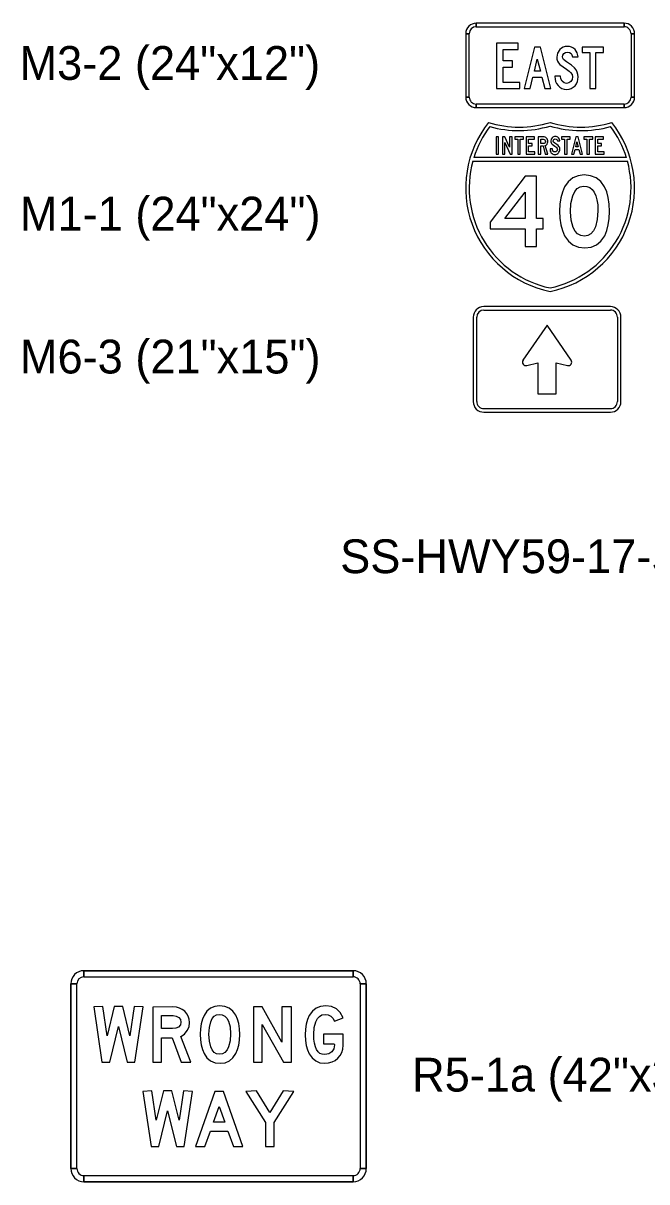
# Model space of a CAD drawing. Extents: x 620856.8 to 620948.6, y 415598.8 to 415658.2.
# Drawn here: x 620913.04 to 620920.43, y 415627.07 to 415640.79 of the extents above; entities that cross this region are included whole.
import ezdxf

# ---------------------------------------------------------------- set-up
doc = ezdxf.new("R2010")
doc.units = 0
doc.layers.add('SIGNS', color=7, linetype='Continuous')

msp = doc.modelspace()

# ---------------------------------------------------------------- linework, layer by layer
at = {"layer": 'SIGNS'}
for p, q in [((620918.405, 415640.745), (620918.405, 415640.787)), ((620920.155, 415640.787), (620920.155, 415640.745)), ((620918.28, 415640.662), (620918.321, 415640.662)), ((620920.238, 415640.662), (620920.28, 415640.662)), ((620918.321, 415639.912), (620918.28, 415639.912)), ((620920.28, 415639.912), (620920.238, 415639.912)), ((620918.405, 415639.787), (620918.405, 415639.829)), ((620920.155, 415639.829), (620920.155, 415639.787)), ((620918.668, 415639.441), (620918.639, 415639.441)), ((620918.639, 415639.441), (620918.639, 415639.236)), ((620918.668, 415639.236), (620918.668, 415639.441)), ((620918.742, 415639.441), (620918.714, 415639.441)), ((620918.714, 415639.441), (620918.714, 415639.236)), ((620918.798, 415639.319), (620918.742, 415639.441)), ((620918.742, 415639.236), (620918.742, 415639.374)), ((620918.742, 415639.374), (620918.806, 415639.236)), ((620918.829, 415639.441), (620918.798, 415639.441)), ((620918.798, 415639.441), (620918.798, 415639.319)), ((620918.829, 415639.236), (620918.829, 415639.441)), ((620918.965, 415639.441), (620918.86, 415639.441)), ((620918.86, 415639.441), (620918.86, 415639.415)), ((620918.86, 415639.415), (620918.897, 415639.415)), ((620918.897, 415639.415), (620918.897, 415639.236)), ((620918.927, 415639.236), (620918.927, 415639.415)), ((620918.927, 415639.415), (620918.965, 415639.415)), ((620918.965, 415639.415), (620918.965, 415639.441)), ((620919.093, 415639.441), (620918.995, 415639.441)), ((620918.995, 415639.441), (620918.995, 415639.236)), ((620919.025, 415639.361), (620919.025, 415639.413)), ((620919.025, 415639.413), (620919.093, 415639.413)), ((620919.068, 415639.361), (620919.025, 415639.361)), ((620919.025, 415639.264), (620919.025, 415639.333)), ((620919.025, 415639.333), (620919.068, 415639.333)), ((620919.068, 415639.333), (620919.068, 415639.361)), ((620919.093, 415639.413), (620919.093, 415639.441)), ((620919.292, 415639.412), (620919.288, 415639.392)), ((620919.288, 415639.392), (620919.289, 415639.382)), ((620919.289, 415639.382), (620919.292, 415639.372)), ((620919.303, 415639.429), (620919.292, 415639.412)), ((620919.292, 415639.372), (620919.297, 415639.364)), ((620919.297, 415639.364), (620919.303, 415639.356)), ((620919.311, 415639.436), (620919.303, 415639.429)), ((620919.303, 415639.356), (620919.337, 415639.332)), ((620919.32, 415639.441), (620919.311, 415639.436)), ((620919.316, 415639.393), (620919.318, 415639.402)), ((620919.317, 415639.386), (620919.316, 415639.393)), ((620919.321, 415639.38), (620919.317, 415639.386)), ((620919.318, 415639.402), (620919.324, 415639.41)), ((620919.33, 415639.444), (620919.32, 415639.441)), ((620919.336, 415639.368), (620919.321, 415639.38)), ((620919.324, 415639.41), (620919.332, 415639.415)), ((620919.34, 415639.445), (620919.33, 415639.444)), ((620919.332, 415639.415), (620919.341, 415639.417)), ((620919.36, 415639.352), (620919.336, 415639.368)), ((620919.337, 415639.332), (620919.349, 415639.323)), ((620919.351, 415639.444), (620919.34, 415639.445)), ((620919.341, 415639.417), (620919.351, 415639.415)), ((620919.349, 415639.323), (620919.357, 415639.316)), ((620919.362, 415639.441), (620919.351, 415639.444)), ((620919.351, 415639.415), (620919.358, 415639.41)), ((620919.358, 415639.41), (620919.362, 415639.403)), ((620919.376, 415639.339), (620919.36, 415639.352)), ((620919.371, 415639.436), (620919.362, 415639.441)), ((620919.362, 415639.403), (620919.366, 415639.393)), ((620919.366, 415639.393), (620919.394, 415639.393)), ((620919.378, 415639.43), (620919.371, 415639.436)), ((620919.384, 415639.329), (620919.376, 415639.339)), ((620919.389, 415639.414), (620919.378, 415639.43)), ((620919.389, 415639.318), (620919.384, 415639.329)), ((620919.394, 415639.393), (620919.389, 415639.414)), ((620919.519, 415639.441), (620919.414, 415639.441)), ((620919.414, 415639.441), (620919.414, 415639.415)), ((620919.414, 415639.415), (620919.451, 415639.415)), ((620919.451, 415639.415), (620919.451, 415639.236)), ((620919.481, 415639.236), (620919.481, 415639.415)), ((620919.481, 415639.415), (620919.519, 415639.415)), ((620919.519, 415639.415), (620919.519, 415639.441)), ((620919.784, 415639.441), (620919.679, 415639.441)), ((620919.679, 415639.441), (620919.679, 415639.415)), ((620919.679, 415639.415), (620919.716, 415639.415)), ((620919.716, 415639.415), (620919.716, 415639.236)), ((620919.746, 415639.236), (620919.746, 415639.415)), ((620919.746, 415639.415), (620919.784, 415639.415)), ((620919.784, 415639.415), (620919.784, 415639.441)), ((620919.911, 415639.441), (620919.814, 415639.441)), ((620919.814, 415639.441), (620919.814, 415639.236)), ((620919.844, 415639.361), (620919.844, 415639.413)), ((620919.844, 415639.413), (620919.911, 415639.413)), ((620919.887, 415639.361), (620919.844, 415639.361)), ((620919.844, 415639.264), (620919.844, 415639.333)), ((620919.844, 415639.333), (620919.887, 415639.333)), ((620919.887, 415639.333), (620919.887, 415639.361)), ((620919.911, 415639.413), (620919.911, 415639.441)), ((620920.183, 415639.195), (620918.376, 415639.195)), ((620918.639, 415639.236), (620918.668, 415639.236)), ((620918.714, 415639.236), (620918.742, 415639.236)), ((620918.806, 415639.236), (620918.829, 415639.236)), ((620918.897, 415639.236), (620918.927, 415639.236)), ((620918.995, 415639.236), (620919.1, 415639.236)), ((620919.1, 415639.264), (620919.025, 415639.264)), ((620919.1, 415639.236), (620919.1, 415639.264)), ((620919.307, 415639.298), (620919.279, 415639.298)), ((620919.279, 415639.298), (620919.279, 415639.296)), ((620919.279, 415639.296), (620919.279, 415639.284)), ((620919.279, 415639.284), (620919.282, 415639.272)), ((620919.282, 415639.272), (620919.287, 415639.261)), ((620919.287, 415639.261), (620919.294, 415639.252)), ((620919.294, 415639.252), (620919.303, 415639.243)), ((620919.303, 415639.243), (620919.313, 415639.237)), ((620919.308, 415639.284), (620919.307, 415639.298)), ((620919.314, 415639.273), (620919.308, 415639.284)), ((620919.313, 415639.237), (620919.324, 415639.234)), ((620919.324, 415639.265), (620919.314, 415639.273)), ((620919.336, 415639.262), (620919.324, 415639.265)), ((620919.324, 415639.234), (620919.336, 415639.232)), ((620919.348, 415639.265), (620919.336, 415639.262)), ((620919.336, 415639.232), (620919.349, 415639.234)), ((620919.358, 415639.272), (620919.348, 415639.265)), ((620919.349, 415639.234), (620919.36, 415639.237)), ((620919.357, 415639.316), (620919.363, 415639.305)), ((620919.364, 415639.282), (620919.358, 415639.272)), ((620919.36, 415639.237), (620919.37, 415639.243)), ((620919.363, 415639.305), (620919.366, 415639.295)), ((620919.366, 415639.295), (620919.364, 415639.282)), ((620919.37, 415639.243), (620919.378, 415639.251)), ((620919.378, 415639.251), (620919.385, 415639.261)), ((620919.385, 415639.261), (620919.39, 415639.271)), ((620919.393, 415639.307), (620919.389, 415639.318)), ((620919.39, 415639.271), (620919.393, 415639.282)), ((620919.394, 415639.295), (620919.393, 415639.307)), ((620919.393, 415639.282), (620919.394, 415639.295)), ((620919.451, 415639.236), (620919.481, 415639.236)), ((620919.716, 415639.236), (620919.746, 415639.236)), ((620919.814, 415639.236), (620919.919, 415639.236)), ((620919.919, 415639.264), (620919.844, 415639.264)), ((620919.919, 415639.236), (620919.919, 415639.264)), ((620919.994, 415637.432), (620918.494, 415637.432)), ((620918.369, 415637.307), (620918.369, 415636.307)), ((620918.41, 415636.307), (620918.41, 415637.307)), ((620918.494, 415637.39), (620919.994, 415637.39)), ((620920.077, 415637.307), (620920.077, 415636.307)), ((620920.119, 415636.307), (620920.119, 415637.307)), ((620919.244, 415637.213), (620918.958, 415636.798)), ((620919.529, 415636.798), (620919.244, 415637.213)), ((620919.003, 415636.735), (620919.134, 415636.765)), ((620919.134, 415636.765), (620919.134, 415636.4)), ((620919.353, 415636.4), (620919.353, 415636.765)), ((620919.353, 415636.765), (620919.484, 415636.735)), ((620919.134, 415636.4), (620919.353, 415636.4)), ((620919.994, 415636.223), (620918.494, 415636.223)), ((620918.494, 415636.182), (620919.994, 415636.182)), ((620916.947, 415629.57), (620913.759, 415629.57)), ((620913.759, 415629.497), (620913.759, 415629.57)), ((620916.947, 415629.57), (620913.759, 415629.57)), ((620913.759, 415629.57), (620916.947, 415629.57)), ((620916.947, 415629.57), (620916.947, 415629.497)), ((620913.603, 415629.414), (620913.603, 415627.227)), ((620913.603, 415629.414), (620913.676, 415629.414)), ((620913.603, 415629.414), (620913.603, 415627.227)), ((620913.603, 415627.227), (620913.603, 415629.414)), ((620917.03, 415629.414), (620917.103, 415629.414)), ((620917.103, 415627.227), (620917.103, 415629.414)), ((620917.103, 415627.227), (620917.103, 415629.414)), ((620917.103, 415629.414), (620917.103, 415627.227)), ((620913.676, 415627.227), (620913.603, 415627.227)), ((620913.759, 415627.07), (620913.759, 415627.143)), ((620916.947, 415627.143), (620916.947, 415627.07)), ((620917.103, 415627.227), (620917.03, 415627.227)), ((620913.759, 415627.07), (620916.947, 415627.07)), ((620913.759, 415627.07), (620916.947, 415627.07)), ((620916.947, 415627.07), (620913.759, 415627.07))]:
    msp.add_line(p, q, dxfattribs=at)
for points in [[(620920.155, 415640.787), (620918.405, 415640.787), (620918.405, 415640.745), (620920.155, 415640.745), (620920.155, 415640.787), (620920.155, 415640.787)], [(620918.28, 415640.662), (620918.28, 415639.912), (620918.321, 415639.912), (620918.321, 415640.662), (620918.28, 415640.662), (620918.28, 415640.662)], [(620920.28, 415639.912), (620920.28, 415640.662), (620920.238, 415640.662), (620920.238, 415639.912), (620920.28, 415639.912), (620920.28, 415639.912)], [(620918.921, 415640.086), (620918.722, 415640.086), (620918.722, 415640.266), (620918.835, 415640.266), (620918.835, 415640.34), (620918.722, 415640.34), (620918.722, 415640.477), (620918.9, 415640.477), (620918.9, 415640.551), (620918.643, 415640.551), (620918.643, 415640.012), (620918.921, 415640.012)], [(620919.336, 415640.159), (620919.336, 415640.155), (620919.338, 415640.125), (620919.345, 415640.097), (620919.357, 415640.072), (620919.374, 415640.049), (620919.395, 415640.028), (620919.419, 415640.014), (620919.446, 415640.005), (620919.475, 415640.002), (620919.504, 415640.005), (620919.531, 415640.014), (620919.554, 415640.028), (620919.575, 415640.047), (620919.592, 415640.07), (620919.603, 415640.095), (620919.61, 415640.122), (620919.613, 415640.152), (620919.61, 415640.181), (620919.602, 415640.208), (620919.588, 415640.233), (620919.569, 415640.257), (620919.532, 415640.289), (620919.475, 415640.328), (620919.437, 415640.357), (620919.429, 415640.371), (620919.426, 415640.387), (620919.431, 415640.409), (620919.444, 415640.428), (620919.463, 415640.44), (620919.486, 415640.444), (620919.51, 415640.44), (620919.528, 415640.429), (620919.537, 415640.412), (620919.545, 415640.387), (620919.613, 415640.387), (620919.602, 415640.437), (620919.576, 415640.477), (620919.557, 415640.492), (620919.535, 415640.503), (620919.511, 415640.51), (620919.484, 415640.512), (620919.459, 415640.51), (620919.436, 415640.503), (620919.414, 415640.491), (620919.395, 415640.474), (620919.367, 415640.433), (620919.358, 415640.385), (620919.36, 415640.361), (620919.367, 415640.338), (620919.379, 415640.317), (620919.396, 415640.298), (620919.475, 415640.241), (620919.505, 415640.219), (620919.523, 415640.202), (620919.539, 415640.178), (620919.545, 415640.151), (620919.54, 415640.122), (620919.526, 415640.098), (620919.503, 415640.08), (620919.475, 415640.074), (620919.445, 415640.08), (620919.421, 415640.101), (620919.408, 415640.127), (620919.404, 415640.159)], [(620919.75, 415640.012), (620919.822, 415640.012), (620919.822, 415640.441), (620919.913, 415640.441), (620919.913, 415640.502), (620919.661, 415640.502), (620919.661, 415640.441), (620919.75, 415640.441)], [(620918.405, 415639.787), (620920.155, 415639.787), (620920.155, 415639.829), (620918.405, 415639.829), (620918.405, 415639.787), (620918.405, 415639.787)], [(620916.947, 415629.57), (620913.759, 415629.57), (620913.759, 415629.497), (620916.947, 415629.497), (620916.947, 415629.57), (620916.947, 415629.57)], [(620913.603, 415629.414), (620913.603, 415627.227), (620913.676, 415627.227), (620913.676, 415629.414), (620913.603, 415629.414), (620913.603, 415629.414)], [(620917.103, 415627.227), (620917.103, 415629.414), (620917.03, 415629.414), (620917.03, 415627.227), (620917.103, 415627.227), (620917.103, 415627.227)], [(620913.874, 415629.141), (620913.971, 415628.487), (620914.064, 415628.487), (620914.166, 415628.91), (620914.27, 415628.487), (620914.363, 415628.487), (620914.461, 415629.141), (620914.354, 415629.146), (620914.303, 415628.799), (620914.218, 415629.146), (620914.115, 415629.146), (620914.032, 415628.799), (620913.981, 415629.146)], [(620915.768, 415628.487), (620915.87, 415628.487), (620915.87, 415628.933), (620916.123, 415628.487), (620916.216, 415628.487), (620916.216, 415629.141), (620916.101, 415629.141), (620916.101, 415628.725), (620915.87, 415629.141), (620915.768, 415629.141)], [(620916.827, 415628.82), (620916.597, 415628.82), (620916.597, 415628.705), (620916.724, 415628.705), (620916.725, 415628.692), (620916.717, 415628.646), (620916.694, 415628.609), (620916.658, 415628.585), (620916.61, 415628.577), (620916.58, 415628.58), (620916.554, 415628.591), (620916.532, 415628.61), (620916.514, 415628.636), (620916.5, 415628.67), (620916.49, 415628.711), (620916.483, 415628.759), (620916.482, 415628.815), (620916.487, 415628.898), (620916.505, 415628.965), (620916.524, 415629.002), (620916.549, 415629.029), (620916.578, 415629.046), (620916.614, 415629.051), (620916.652, 415629.046), (620916.683, 415629.031), (620916.708, 415629.007), (620916.727, 415628.973), (620916.827, 415629.011), (620916.795, 415629.073), (620916.75, 415629.118), (620916.692, 415629.145), (620916.622, 415629.154), (620916.561, 415629.146), (620916.508, 415629.125), (620916.464, 415629.09), (620916.428, 415629.04), (620916.407, 415628.992), (620916.391, 415628.938), (620916.382, 415628.876), (620916.379, 415628.809), (620916.382, 415628.745), (620916.391, 415628.686), (620916.406, 415628.633), (620916.428, 415628.586), (620916.462, 415628.537), (620916.505, 415628.502), (620916.554, 415628.481), (620916.612, 415628.474), (620916.657, 415628.478), (620916.698, 415628.489), (620916.735, 415628.507), (620916.767, 415628.533), (620916.793, 415628.564), (620916.812, 415628.601), (620916.823, 415628.641), (620916.827, 415628.687)], [(620914.457, 415628.141), (620914.555, 415627.487), (620914.647, 415627.487), (620914.749, 415627.91), (620914.853, 415627.487), (620914.947, 415627.487), (620915.044, 415628.141), (620914.937, 415628.146), (620914.886, 415627.799), (620914.801, 415628.146), (620914.699, 415628.146), (620914.615, 415627.799), (620914.564, 415628.146)], [(620915.676, 415628.141), (620915.908, 415627.773), (620915.908, 415627.487), (620916.013, 415627.487), (620916.013, 415627.773), (620916.243, 415628.141), (620916.119, 415628.146), (620915.959, 415627.893), (620915.802, 415628.146)], [(620913.759, 415627.07), (620916.947, 415627.07), (620916.947, 415627.143), (620913.759, 415627.143), (620913.759, 415627.07), (620913.759, 415627.07)]]:
    msp.add_lwpolyline(points, close=True, dxfattribs=at)
for points in [[(620918.971, 415640.012), (620919.042, 415640.012), (620919.075, 415640.147), (620919.181, 415640.147), (620919.216, 415640.012), (620919.287, 415640.012), (620919.164, 415640.502), (620919.095, 415640.502), (620918.971, 415640.012)], [(620919.093, 415640.217), (620919.127, 415640.359), (620919.164, 415640.217), (620919.093, 415640.217)], [(620918.549, 415639.611), (620918.549, 415639.611)], [(620920.01, 415639.611), (620920.01, 415639.611)], [(620918.565, 415639.563), (620918.565, 415639.563)], [(620919.28, 415639.57), (620919.28, 415639.57)], [(620919.995, 415639.563), (620919.995, 415639.563)], [(620919.169, 415639.236), (620919.169, 415639.334), (620919.196, 415639.334), (620919.223, 415639.236), (620919.252, 415639.236), (620919.223, 415639.337), (620919.235, 415639.344), (620919.245, 415639.356), (620919.25, 415639.369), (620919.252, 415639.384), (620919.251, 415639.396), (620919.249, 415639.407), (620919.244, 415639.416), (620919.238, 415639.425), (620919.23, 415639.432), (620919.221, 415639.437), (620919.21, 415639.44), (620919.198, 415639.441), (620919.137, 415639.441), (620919.137, 415639.236), (620919.169, 415639.236)], [(620919.169, 415639.361), (620919.169, 415639.413), (620919.199, 415639.413), (620919.209, 415639.411), (620919.218, 415639.406), (620919.223, 415639.397), (620919.225, 415639.387), (620919.223, 415639.375), (620919.219, 415639.367), (620919.211, 415639.362), (620919.2, 415639.361), (620919.169, 415639.361)], [(620919.562, 415639.236), (620919.576, 415639.293), (620919.62, 415639.293), (620919.635, 415639.236), (620919.665, 415639.236), (620919.613, 415639.441), (620919.584, 415639.441), (620919.533, 415639.236), (620919.562, 415639.236)], [(620919.583, 415639.322), (620919.598, 415639.381), (620919.613, 415639.322), (620919.583, 415639.322)], [(620918.364, 415639.153), (620918.906, 415639.153), (620919.433, 415639.153), (620920.196, 415639.153)], [(620918.985, 415638.144), (620919.117, 415638.144), (620919.117, 415638.352), (620919.196, 415638.352), (620919.196, 415638.473), (620919.117, 415638.473), (620919.117, 415638.974), (620918.985, 415638.974), (620918.568, 415638.431), (620918.568, 415638.352), (620918.985, 415638.352), (620918.985, 415638.144)], [(620919.684, 415638.99), (620919.611, 415638.981), (620919.548, 415638.955), (620919.495, 415638.91), (620919.452, 415638.848), (620919.425, 415638.787), (620919.405, 415638.72), (620919.393, 415638.645), (620919.39, 415638.563), (620919.393, 415638.477), (620919.405, 415638.4), (620919.425, 415638.331), (620919.452, 415638.27), (620919.496, 415638.207), (620919.55, 415638.163), (620919.615, 415638.136), (620919.691, 415638.127), (620919.765, 415638.136), (620919.829, 415638.163), (620919.882, 415638.208), (620919.926, 415638.271), (620919.951, 415638.331), (620919.969, 415638.398), (620919.98, 415638.474), (620919.984, 415638.558), (620919.98, 415638.644), (620919.969, 415638.722), (620919.951, 415638.79), (620919.925, 415638.85), (620919.881, 415638.911), (620919.826, 415638.955), (620919.76, 415638.981), (620919.684, 415638.99)], [(620918.985, 415638.473), (620918.745, 415638.473), (620918.985, 415638.787), (620918.985, 415638.473)], [(620919.846, 415638.567), (620919.838, 415638.463), (620919.817, 415638.377), (620919.793, 415638.329), (620919.764, 415638.294), (620919.728, 415638.273), (620919.686, 415638.266), (620919.643, 415638.272), (620919.606, 415638.292), (620919.576, 415638.324), (620919.551, 415638.37), (620919.528, 415638.454), (620919.52, 415638.555), (620919.527, 415638.654), (620919.55, 415638.743), (620919.573, 415638.794), (620919.601, 415638.83), (620919.636, 415638.851), (620919.676, 415638.859), (620919.716, 415638.854), (620919.75, 415638.841), (620919.779, 415638.818), (620919.803, 415638.786), (620919.821, 415638.744), (620919.835, 415638.694), (620919.843, 415638.635), (620919.846, 415638.567)], [(620919.28, 415637.653), (620919.28, 415637.653)], [(620919.28, 415637.611), (620919.28, 415637.611)], [(620914.575, 415628.487), (620914.678, 415628.487), (620914.678, 415628.774), (620914.803, 415628.774), (620914.909, 415628.487), (620915.023, 415628.487), (620914.907, 415628.792), (620914.949, 415628.82), (620914.982, 415628.86), (620915.003, 415628.906), (620915.01, 415628.956), (620915.006, 415628.995), (620914.995, 415629.03), (620914.977, 415629.061), (620914.952, 415629.089), (620914.922, 415629.112), (620914.889, 415629.128), (620914.853, 415629.137), (620914.813, 415629.141), (620914.575, 415629.14), (620914.575, 415628.487)], [(620914.678, 415628.884), (620914.678, 415629.038), (620914.814, 415629.038), (620914.85, 415629.033), (620914.881, 415629.017), (620914.901, 415628.993), (620914.908, 415628.961), (620914.901, 415628.927), (620914.878, 415628.902), (620914.846, 415628.888), (620914.809, 415628.884), (620914.678, 415628.884)], [(620915.604, 415628.814), (620915.601, 415628.883), (620915.592, 415628.944), (620915.577, 415628.997), (620915.557, 415629.044), (620915.522, 415629.092), (620915.479, 415629.126), (620915.427, 415629.147), (620915.366, 415629.154), (620915.308, 415629.147), (620915.258, 415629.126), (620915.216, 415629.091), (620915.182, 415629.041), (620915.162, 415628.995), (620915.148, 415628.942), (620915.139, 415628.883), (620915.136, 415628.819), (620915.139, 415628.751), (620915.148, 415628.691), (620915.162, 415628.637), (620915.182, 415628.59), (620915.216, 415628.539), (620915.259, 415628.503), (620915.311, 415628.481), (620915.372, 415628.474), (620915.43, 415628.481), (620915.481, 415628.503), (620915.523, 415628.538), (620915.557, 415628.588), (620915.578, 415628.636), (620915.593, 415628.689), (620915.601, 415628.749), (620915.604, 415628.814)], [(620915.495, 415628.822), (620915.489, 415628.738), (620915.472, 415628.669), (620915.453, 415628.631), (620915.428, 415628.603), (620915.398, 415628.587), (620915.363, 415628.581), (620915.33, 415628.587), (620915.302, 415628.603), (620915.278, 415628.631), (620915.26, 415628.669), (620915.244, 415628.736), (620915.239, 415628.817), (620915.244, 415628.896), (620915.26, 415628.964), (620915.278, 415629.003), (620915.301, 415629.031), (620915.329, 415629.048), (620915.361, 415629.053), (620915.396, 415629.048), (620915.427, 415629.033), (620915.452, 415629.007), (620915.471, 415628.972), (620915.489, 415628.905), (620915.495, 415628.822)], [(620915.08, 415627.487), (620915.191, 415627.487), (620915.257, 415627.671), (620915.464, 415627.671), (620915.529, 415627.487), (620915.64, 415627.487), (620915.412, 415628.141), (620915.308, 415628.141), (620915.08, 415627.487)], [(620915.293, 415627.777), (620915.361, 415627.962), (620915.426, 415627.777), (620915.293, 415627.777)]]:
    msp.add_lwpolyline(points, dxfattribs=at)
for centre, radius, start, end in [((620918.405, 415640.662), 0.125, 90.0002, 179.9998), ((620918.405, 415640.662), 0.0833, 90.0002, 179.9998), ((620920.155, 415640.662), 0.125, 0, 90.0002), ((620920.155, 415640.662), 0.0833, 0, 90.0002), ((620918.405, 415639.912), 0.125, 179.9998, 270.0001), ((620918.405, 415639.912), 0.0833, 179.9998, 270.0001), ((620920.155, 415639.912), 0.125, 270.0001, 0.0003), ((620920.155, 415639.912), 0.0833, 270.0001, 0.0003), ((620919.53, 415638.836), 1.25, 141.669, 258.463), ((620918.914, 415640.807), 1.25, 253.009, 286.9909), ((620919.03, 415638.836), 1.25, 281.5371, 38.3311), ((620919.645, 415640.807), 1.25, 253.0091, 286.9911), ((620919.529, 415638.835), 1.208, 142.9959, 162.6952), ((620918.911, 415640.808), 1.292, 254.4391, 286.5746), ((620919.648, 415640.808), 1.292, 253.4255, 285.561), ((620919.03, 415638.835), 1.208, 17.3047, 37.0041), ((620919.529, 415638.835), 1.208, 164.7534, 258.0704), ((620919.03, 415638.835), 1.208, 281.9296, 15.2467), ((620919.03, 415638.835), 1.208, 281.9296118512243, 281.9296385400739), ((620919.529, 415638.835), 1.208, 258.0704, 258.0705), ((620918.494, 415637.307), 0.125, 90.0002, 179.9998), ((620919.994, 415637.307), 0.125, 360, 90.0002), ((620918.494, 415637.307), 0.0833, 90.0002, 179.9998), ((620919.994, 415637.307), 0.0833, 360, 90.0002), ((620918.994, 415636.775), 0.0417, 147.7246, 282.9506), ((620919.494, 415636.775), 0.0417, 257.0495, 32.2756), ((620918.494, 415636.307), 0.125, 179.9998, 270.0001), ((620918.494, 415636.307), 0.0833, 179.9998, 270.0001), ((620919.994, 415636.307), 0.125, 270.0001, 0.0003), ((620919.994, 415636.307), 0.0833, 270.0001, 0.0003), ((620913.759, 415629.414), 0.156, 90.0002, 179.9998), ((620913.759, 415629.414), 0.156, 90.0002, 179.9998), ((620913.759, 415629.414), 0.156, 90.0002, 179.9998), ((620913.759, 415629.414), 0.156, 90.0002, 179.9998), ((620913.759, 415629.414), 0.0833, 90.0002, 179.9998), ((620916.947, 415629.414), 0.156, 0, 90.0002), ((620916.947, 415629.414), 0.156, 0, 90.0002), ((620916.947, 415629.414), 0.156, 0, 90.0002), ((620916.947, 415629.414), 0.156, 0, 90.0002), ((620916.947, 415629.414), 0.0833, 0, 90.0002), ((620913.759, 415627.227), 0.156, 179.9998, 270.0001), ((620913.759, 415627.227), 0.156, 179.9998, 270.0001), ((620913.759, 415627.227), 0.156, 179.9998, 270.0001), ((620913.759, 415627.227), 0.156, 179.9998, 270.0001), ((620913.759, 415627.227), 0.0833, 179.9998, 270.0001), ((620916.947, 415627.227), 0.156, 270.0001, 0.0003), ((620916.947, 415627.227), 0.156, 270.0001, 0.0003), ((620916.947, 415627.227), 0.0833, 270.0001, 0.0003), ((620916.947, 415627.227), 0.156, 270.0001, 0.0003), ((620916.947, 415627.227), 0.156, 270.0001, 0.0003)]:
    msp.add_arc(centre, radius, start, end, dxfattribs=at)

# ---------------------------------------------------------------- texts
for s, p in [('M3-2 (24"x12")', (620912.995, 415640.116)), ('M1-1 (24"x24")', (620913, 415638.332)), ('M6-3 (21"x15")', (620913, 415636.64)), ('SS-HWY59-17-STA44+00SB', (620916.793, 415634.276)), ('R5-1a (42"x30")', (620917.645, 415628.139))]:
    msp.add_text(s, height=0.4, rotation=0, dxfattribs=at).set_placement(p)

doc.saveas('drawing.dxf')
